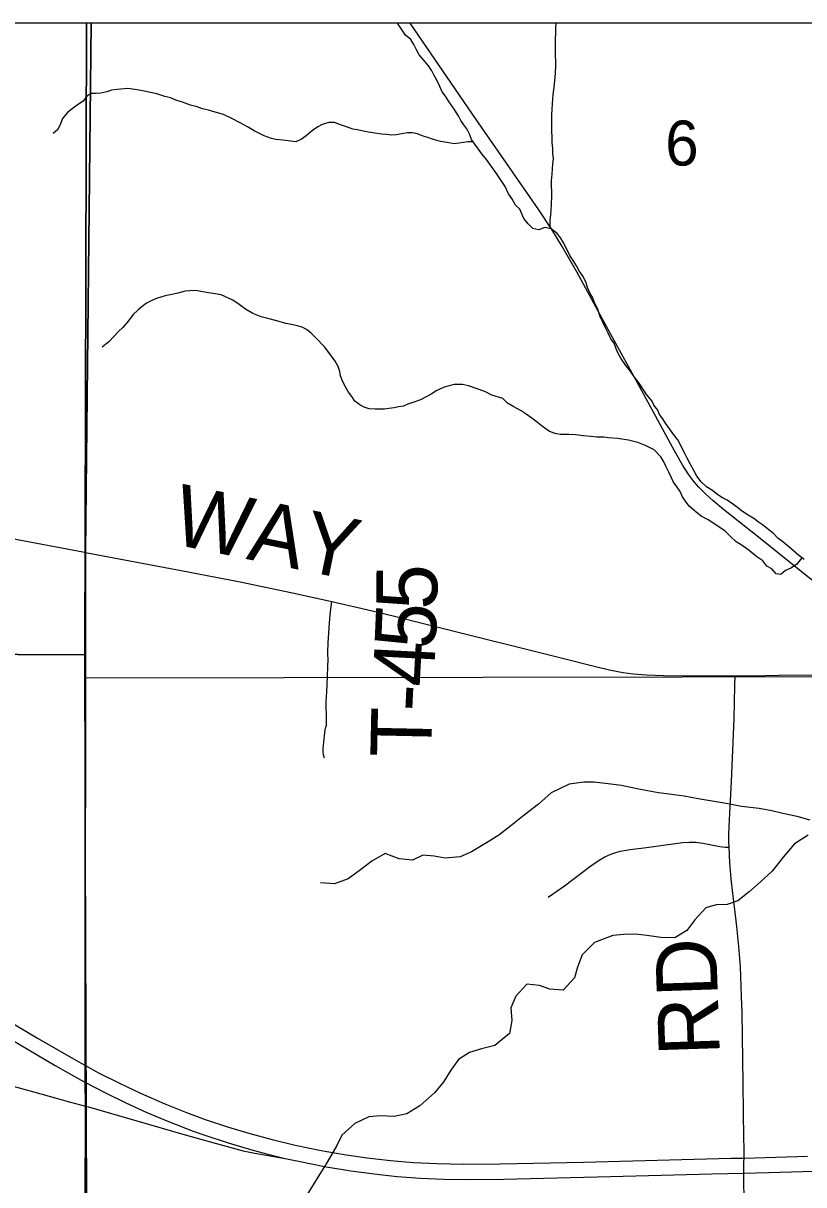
# Model space of a CAD drawing. Extents: x 0 to 34, y 0 to 22.
# Drawn here: x 5.719 to 6.446, y 19.817 to 20.9 of the extents above; entities that cross this region are included whole.
import ezdxf

# ---------------------------------------------------------------- set-up
doc = ezdxf.new("R2010")
doc.units = 0
for name, color, linetype in [('GM_X_County_Road', 7, 'Continuous'), ('GM_X_County_Road_Text', 7, 'Continuous'), ('GM_X_Minor_River', 7, 'Continuous'), ('GM_X_Section', 7, 'Continuous'), ('GM_X_Section_Text', 7, 'Continuous'), ('GM_X_State_Route', 7, 'Continuous'), ('GM_X_Township_Road', 7, 'Continuous'), ('GM_X_Township_Road_Text', 7, 'Continuous'), ('GM_X_Unincorporated', 7, 'Continuous'), ('GM_X_US_Route', 7, 'Continuous')]:
    doc.layers.add(name, color=color, linetype=linetype)

msp = doc.modelspace()

# ---------------------------------------------------------------- linework, layer by layer
at = {"layer": 'GM_X_County_Road'}
for points in [[(5.1695, 20.4986), (5.1854, 20.4986), (5.2065, 20.4983), (5.2294, 20.4982), (5.2496, 20.4977), (5.2723, 20.4972), (5.283, 20.4965), (5.2939, 20.4954), (5.3034, 20.4942), (5.3248, 20.4906), (5.3554, 20.485), (5.5022, 20.458), (5.5359, 20.4518), (5.6032, 20.4392), (5.6277, 20.4348), (5.7314, 20.4153), (5.7741, 20.4072), (5.7768, 20.4067)], [(5.7768, 20.4067), (5.8658, 20.3898), (5.9207, 20.3791), (5.9694, 20.369), (6.0063, 20.3609)], [(6.0063, 20.3609), (6.0331, 20.3547), (6.0633, 20.3474), (6.0904, 20.3407), (6.1327, 20.3302), (6.19, 20.3159), (6.2235, 20.3073), (6.2443, 20.3021), (6.253, 20.2999), (6.261, 20.298), (6.2661, 20.297), (6.2777, 20.2947), (6.287, 20.2935), (6.2995, 20.2924), (6.3151, 20.2918), (6.3493, 20.2915), (6.3791, 20.2915), (6.382, 20.2915)], [(6.382, 20.2915), (6.3969, 20.2916), (6.4231, 20.2921), (6.4788, 20.2924), (6.5063, 20.2926)]]:
    msp.add_lwpolyline(points, dxfattribs=at)
at = {"layer": 'GM_X_Minor_River'}
for points in [[(6.1626, 20.7551), (6.1591, 20.7608), (6.1548, 20.7664), (6.1502, 20.7728), (6.1459, 20.7781), (6.1428, 20.7826), (6.1394, 20.7871), (6.1363, 20.7916), (6.1347, 20.7958), (6.1319, 20.8015), (6.1292, 20.8052), (6.1265, 20.8094), (6.1242, 20.8135), (6.1195, 20.8207), (6.1153, 20.8271), (6.1122, 20.832), (6.1091, 20.8361), (6.1067, 20.841), (6.104, 20.847), (6.1016, 20.8512), (6.0993, 20.8557), (6.0962, 20.8602), (6.0916, 20.8659), (6.0877, 20.8704), (6.085, 20.8753), (6.0826, 20.8802), (6.0799, 20.8847), (6.0749, 20.8888), (6.0679, 20.899), (6.0673, 20.9)], [(6.2097, 20.7084), (6.2095, 20.7163), (6.2102, 20.7216), (6.2105, 20.7254), (6.2108, 20.7315), (6.2111, 20.7383), (6.2109, 20.7531), (6.2116, 20.7592), (6.2119, 20.7642), (6.2122, 20.7687), (6.2126, 20.7737), (6.2121, 20.7782), (6.2121, 20.7831), (6.2116, 20.7888), (6.2115, 20.7945), (6.2111, 20.7991), (6.211, 20.8029), (6.2113, 20.8101), (6.2113, 20.815), (6.2116, 20.8196), (6.2122, 20.8295), (6.2125, 20.8333), (6.2132, 20.8405), (6.2139, 20.8462), (6.2146, 20.8535), (6.2149, 20.8607), (6.2147, 20.8736), (6.2146, 20.8793), (6.2145, 20.885), (6.2148, 20.8907), (6.2148, 20.8956), (6.2153, 20.9)], [(6.1379, 20.7893), (6.1329, 20.7893), (6.1249, 20.7881), (6.1203, 20.7876), (6.1135, 20.7887), (6.1074, 20.7897), (6.1009, 20.7915), (6.0955, 20.7934), (6.0913, 20.7948), (6.086, 20.7967), (6.0814, 20.7977), (6.0768, 20.7977), (6.0662, 20.796), (6.062, 20.7956), (6.0571, 20.7963), (6.0525, 20.7966), (6.0483, 20.7973), (6.0422, 20.798), (6.0369, 20.799), (6.03, 20.8005), (6.0258, 20.8012), (6.0197, 20.8034), (6.0144, 20.8052), (6.0086, 20.8074), (6.0033, 20.8073), (5.9973, 20.8057), (5.9931, 20.8034), (5.9882, 20.7999), (5.9822, 20.7949), (5.978, 20.7918), (5.9727, 20.7894), (5.9606, 20.7908), (5.9541, 20.7915), (5.9499, 20.7926), (5.943, 20.7951), (5.9338, 20.7996), (5.9277, 20.8033), (5.9208, 20.807), (5.9131, 20.8111), (5.9051, 20.8148), (5.8975, 20.8169), (5.8914, 20.8188), (5.8856, 20.8202), (5.8807, 20.822), (5.8746, 20.8235), (5.8669, 20.8264), (5.8608, 20.8282), (5.8562, 20.8304), (5.8505, 20.8315), (5.8432, 20.8341), (5.8329, 20.8362), (5.8249, 20.838), (5.8162, 20.839), (5.8063, 20.8381), (5.801, 20.8377), (5.7964, 20.8361), (5.7911, 20.8349), (5.7866, 20.8344), (5.782, 20.8344), (5.7778, 20.832), (5.7745, 20.8274), (5.7703, 20.8244), (5.7654, 20.8212), (5.7602, 20.817), (5.7553, 20.8112), (5.7531, 20.8051), (5.7505, 20.8005), (5.7464, 20.7971)], [(6.4464, 20.4), (6.4414, 20.4037), (6.4337, 20.4104), (6.4264, 20.4164), (6.4218, 20.4198), (6.4179, 20.4239), (6.4118, 20.4288), (6.4075, 20.4325), (6.4037, 20.4347), (6.3995, 20.4381), (6.3941, 20.4414), (6.388, 20.4455), (6.3841, 20.4485), (6.3784, 20.4526), (6.3745, 20.4552), (6.3703, 20.4575), (6.3657, 20.4604), (6.3607, 20.4642), (6.3553, 20.4679), (6.3503, 20.4724), (6.3461, 20.4776), (6.3434, 20.4829), (6.3399, 20.4893), (6.3371, 20.4946), (6.3348, 20.4995), (6.3285, 20.5116), (6.3239, 20.5176), (6.3212, 20.5214), (6.3169, 20.527), (6.3146, 20.5312), (6.3115, 20.5353), (6.3099, 20.5391), (6.3061, 20.544), (6.3045, 20.5477), (6.2998, 20.5534), (6.296, 20.559), (6.2925, 20.5643), (6.2882, 20.5699), (6.284, 20.576), (6.2801, 20.5808), (6.2754, 20.5876), (6.2731, 20.5921), (6.2711, 20.5963), (6.2692, 20.6016), (6.2661, 20.6057), (6.2637, 20.611), (6.261, 20.6159), (6.259, 20.6208), (6.2559, 20.6272), (6.2539, 20.6333), (6.2508, 20.6393), (6.2492, 20.6439), (6.2469, 20.648), (6.2445, 20.6537), (6.243, 20.6578), (6.2402, 20.6639), (6.2367, 20.6691), (6.234, 20.6737), (6.2309, 20.6789), (6.2278, 20.6835), (6.2262, 20.6876), (6.2216, 20.6959), (6.2196, 20.6997), (6.2161, 20.7038), (6.2104, 20.7083), (6.2046, 20.7094), (6.199, 20.7074), (6.1936, 20.7085), (6.189, 20.7129), (6.1851, 20.7178), (6.1812, 20.7265), (6.1774, 20.7303), (6.1739, 20.7367), (6.1708, 20.7408), (6.1676, 20.7476), (6.1653, 20.7514), (6.1626, 20.7551)], [(5.8913, 20.6486), (5.884, 20.65), (5.8795, 20.6507), (5.8738, 20.6506), (5.8696, 20.6502), (5.8628, 20.6482), (5.8586, 20.6474), (5.851, 20.6458), (5.8438, 20.6438), (5.8396, 20.6422), (5.8336, 20.6391), (5.8294, 20.636), (5.8253, 20.6325), (5.8212, 20.6283), (5.8167, 20.6225), (5.8114, 20.6164), (5.8073, 20.6125), (5.8032, 20.6079), (5.7983, 20.6029), (5.7923, 20.5979)], [(6.444, 20.4017), (6.4392, 20.3953), (6.4339, 20.3918), (6.429, 20.3899), (6.4245, 20.386), (6.4203, 20.3867), (6.416, 20.3912), (6.4115, 20.3938), (6.4076, 20.3987), (6.4022, 20.4024), (6.3949, 20.4084), (6.3876, 20.4136), (6.383, 20.4166), (6.3776, 20.4215), (6.3726, 20.4263), (6.3669, 20.4304), (6.3569, 20.4371), (6.3504, 20.4405), (6.3454, 20.4446), (6.3392, 20.4498), (6.3357, 20.4543), (6.333, 20.4585), (6.3307, 20.4634), (6.328, 20.4675), (6.3245, 20.472), (6.3225, 20.4762), (6.3202, 20.4815), (6.3174, 20.4871), (6.3151, 20.4917), (6.3128, 20.4958), (6.3066, 20.5022), (6.2989, 20.5059), (6.2913, 20.5092), (6.2825, 20.5114), (6.2722, 20.5127), (6.2639, 20.5134), (6.2597, 20.5141), (6.2532, 20.514), (6.2479, 20.5147), (6.2406, 20.5154), (6.2334, 20.5164), (6.2269, 20.5167), (6.2193, 20.5166), (6.2151, 20.5173), (6.209, 20.5195), (6.2025, 20.524), (6.1979, 20.5277), (6.1925, 20.5318), (6.1871, 20.5355), (6.1825, 20.5385), (6.1756, 20.5422), (6.1699, 20.5459), (6.1656, 20.5501), (6.1553, 20.5533), (6.1488, 20.5567), (6.1335, 20.5618), (6.1278, 20.5632), (6.1202, 20.5631), (6.1107, 20.5607), (6.1035, 20.5572), (6.0994, 20.5545), (6.0888, 20.549), (6.0816, 20.5463), (6.0771, 20.5447), (6.0729, 20.5431), (6.0684, 20.5423), (6.0642, 20.5415), (6.0593, 20.5407), (6.0551, 20.5402), (6.0467, 20.5401), (6.041, 20.5404), (6.0364, 20.5419), (6.0322, 20.5441), (6.0276, 20.5475), (6.0249, 20.552), (6.0218, 20.5561), (6.0179, 20.5625), (6.0159, 20.5671), (6.0144, 20.5712), (6.0136, 20.5754), (6.012, 20.5799), (6.0092, 20.5848), (6.0058, 20.5897), (5.9996, 20.598), (5.9911, 20.607), (5.9868, 20.6111), (5.9826, 20.6145), (5.9784, 20.6167), (5.9738, 20.6178), (5.9685, 20.6192), (5.9632, 20.6199), (5.9548, 20.6225), (5.9464, 20.6246), (5.9403, 20.6264), (5.9326, 20.6294), (5.9257, 20.6335), (5.9199, 20.6376), (5.9138, 20.6417), (5.9031, 20.6468), (5.8955, 20.6479), (5.8913, 20.6486)], [(6.4517, 20.1571), (6.4396, 20.1605), (6.4263, 20.1634), (6.416, 20.1656), (6.4043, 20.1678), (6.388, 20.1699), (6.3736, 20.1725), (6.3569, 20.1754), (6.3474, 20.1768), (6.3345, 20.1794), (6.3205, 20.1812), (6.3106, 20.1826), (6.3004, 20.1844), (6.289, 20.1866), (6.2761, 20.1892), (6.2636, 20.191), (6.2507, 20.1924), (6.2409, 20.1923), (6.2273, 20.1907), (6.2106, 20.1826), (6.1986, 20.1719), (6.1854, 20.1616), (6.173, 20.1516), (6.1617, 20.1432), (6.1519, 20.1367), (6.1364, 20.1275), (6.1258, 20.1228), (6.1118, 20.1216), (6.1016, 20.1234), (6.091, 20.1245), (6.0812, 20.1198), (6.069, 20.1209), (6.0558, 20.1261), (6.0433, 20.1188), (6.0328, 20.1107), (6.0215, 20.1023), (6.0086, 20.0977), (5.9957, 20.0987)], [(6.4499, 20.1431), (6.4371, 20.135), (6.4266, 20.1224), (6.4164, 20.1095), (6.4055, 20.0995), (6.395, 20.0903), (6.3844, 20.0819), (6.3746, 20.0784), (6.3644, 20.078), (6.3545, 20.0753), (6.3444, 20.0642), (6.3369, 20.0543), (6.3256, 20.0474), (6.3127, 20.0476), (6.2998, 20.0494), (6.2892, 20.0509), (6.2782, 20.0504), (6.268, 20.0496), (6.251, 20.043), (6.2393, 20.0315), (6.2352, 20.0201), (6.2323, 20.0099), (6.2218, 19.9984), (6.2093, 19.9994), (6.1998, 20.0028), (6.188, 20.0042), (6.1775, 19.9931), (6.173, 19.9821), (6.1739, 19.9704), (6.1717, 19.9582), (6.1581, 19.9471), (6.1456, 19.944), (6.1343, 19.9405), (6.1241, 19.934), (6.117, 19.924), (6.1106, 19.9134), (6.102, 19.9031), (6.0881, 19.8908), (6.076, 19.8832), (6.0643, 19.8808), (6.0514, 19.8814), (6.0408, 19.8806), (6.0276, 19.8744), (6.0155, 19.8634), (6.0107, 19.8538), (6.0017, 19.8382), (5.9923, 19.8226), (5.9833, 19.8081)]]:
    msp.add_lwpolyline(points, dxfattribs=at)
at = {"layer": 'GM_X_Section'}
for points in [[(5.415, 19.3104), (5.7798, 19.3134), (5.776, 20.2897), (5.7762, 20.3113), (4.7808, 20.316), (4.783, 19.4891), (5.415, 19.4891)], [(5.776, 20.2897), (6.8888, 20.2917), (6.9057, 19.2783), (5.7801, 19.2683), (5.7798, 19.3134)]]:
    msp.add_lwpolyline(points, close=True, dxfattribs=at)
at = {"layer": 'GM_X_State_Route'}
msp.add_lwpolyline([(6.5254, 20.323), (6.5192, 20.3284), (6.4877, 20.3537), (6.4512, 20.3827), (6.4052, 20.4197), (6.3711, 20.4466), (6.3615, 20.4546), (6.3546, 20.4609), (6.348, 20.4676), (6.3439, 20.4723), (6.3383, 20.4799), (6.3332, 20.4878), (6.3254, 20.5013), (6.2927, 20.5613), (6.2659, 20.6104), (6.2347, 20.6677), (6.2208, 20.6919), (6.2111, 20.7078), (6.1991, 20.7259), (6.169, 20.7694), (6.1406, 20.8102), (6.1056, 20.8615), (6.0793, 20.9)], dxfattribs=at)
at = {"layer": 'GM_X_Township_Road'}
for points in [[(5.7764, 19.7938), (5.7766, 19.8909), (5.7765, 19.9131), (5.7764, 19.9288), (5.7766, 20.4072), (5.7818, 20.9), (2.1, 20.9)], [(8.9, 20.9), (5.7818, 20.9), (5.7766, 20.4072), (5.7764, 19.9288), (5.7765, 19.9131), (5.7766, 19.8909), (5.7764, 19.7938)], [(5.9992, 20.2149), (5.9985, 20.2178), (5.9981, 20.2209), (5.9981, 20.2239), (5.9986, 20.23), (5.999, 20.2328), (5.9993, 20.2359), (5.9997, 20.2386), (6, 20.2413), (6.0005, 20.2438), (6.0012, 20.2456), (6.0013, 20.2483), (6.0012, 20.2543), (6.001, 20.2635), (6.001, 20.2666), (6.0012, 20.2728), (6.0015, 20.2759), (6.002, 20.2911), (6.0025, 20.3004), (6.0029, 20.3068), (6.0027, 20.3081), (6.0025, 20.3104), (6.0025, 20.3133), (6.0026, 20.3163), (6.0028, 20.3194), (6.0029, 20.3224), (6.0034, 20.3317), (6.0041, 20.341), (6.0049, 20.3517), (6.0056, 20.3563), (6.0063, 20.3609)], [(6.3763, 20.132), (6.3762, 20.1365), (6.3762, 20.1438), (6.3764, 20.1512), (6.3771, 20.1637), (6.3785, 20.1931), (6.3809, 20.2514), (6.3818, 20.2827), (6.382, 20.2915)], [(6.2076, 20.0853), (6.2228, 20.0959), (6.2474, 20.1146), (6.2551, 20.1198), (6.2604, 20.1229), (6.266, 20.1254), (6.269, 20.1264), (6.2749, 20.128), (6.2841, 20.1296), (6.2994, 20.1316), (6.3238, 20.135), (6.333, 20.1362), (6.3391, 20.1365), (6.3453, 20.1364), (6.3518, 20.1356), (6.3584, 20.1344), (6.3678, 20.1325), (6.3726, 20.1319), (6.3763, 20.132)], [(6.3901, 19.828), (6.3901, 19.8379), (6.3902, 19.8418), (6.3904, 19.85), (6.3901, 19.8617), (6.3898, 19.8842), (6.3894, 19.9122), (6.3884, 19.9773), (6.388, 19.9928), (6.3868, 20.0207), (6.3855, 20.0393), (6.3836, 20.0578), (6.3813, 20.0762), (6.3798, 20.0886), (6.3782, 20.1023), (6.3771, 20.1172), (6.3763, 20.132)], [(6.3904, 19.8009), (6.3904, 19.8037), (6.3901, 19.8212), (6.3901, 19.828)]]:
    msp.add_lwpolyline(points, dxfattribs=at)
at = {"layer": 'GM_X_Unincorporated'}
for points in [[(5.7777, 20.9), (4.7739, 20.9), (4.7808, 20.316), (5.7762, 20.3113)], [(6.889, 20.9), (5.7777, 20.9), (5.7762, 20.3113), (5.776, 20.2897), (6.8888, 20.2917)]]:
    msp.add_lwpolyline(points, close=True, dxfattribs=at)
at = {"layer": 'GM_X_US_Route'}
for points in [[(5.1444, 20.2539), (5.1454, 20.2536), (5.1495, 20.2523), (5.1602, 20.2489), (5.172, 20.245), (5.1927, 20.2383), (5.2162, 20.23), (5.2365, 20.2222), (5.2565, 20.2137), (5.2763, 20.2047), (5.2959, 20.1951), (5.3151, 20.1849), (5.3395, 20.1712), (5.4224, 20.1222), (5.4704, 20.0934), (5.636, 19.9949), (5.6893, 19.963), (5.7483, 19.9284), (5.7726, 19.9147), (5.7767, 19.9125)], [(5.6521, 20.0015), (5.7321, 19.9538), (5.7697, 19.9321), (5.7766, 19.9283)], [(5.7766, 19.9283), (5.7888, 19.9216), (5.8082, 19.9117), (5.8278, 19.9024), (5.8506, 19.8925), (5.8708, 19.8844), (5.8883, 19.878), (5.9089, 19.8711), (5.9297, 19.8649), (5.9507, 19.8592), (5.9719, 19.8542), (5.9962, 19.8492), (6.0176, 19.8453), (6.0391, 19.8422), (6.0607, 19.8397), (6.0824, 19.8379), (6.1041, 19.8369), (6.129, 19.8364), (6.1631, 19.8365), (6.2407, 19.8382), (6.3783, 19.8419), (6.3902, 19.8418), (6.4492, 19.8438)], [(5.7094, 19.9091), (5.7352, 19.9018), (5.7627, 19.8942), (5.7768, 19.8904)], [(5.7767, 19.9125), (5.7946, 19.9031), (5.8141, 19.8935), (5.8338, 19.8845), (5.8539, 19.8761), (5.877, 19.8672), (5.887, 19.8636), (5.9097, 19.8562), (5.9326, 19.8494), (5.9467, 19.8456), (5.9627, 19.8417)], [(5.7768, 19.8904), (5.7794, 19.8897), (5.8696, 19.8637), (5.8975, 19.8558), (5.9236, 19.8487), (5.9343, 19.8465), (5.9627, 19.8417)], [(6.3901, 19.828), (6.413, 19.8287), (6.4874, 19.8307), (6.5375, 19.8321), (6.5944, 19.8337), (6.6691, 19.8354), (6.686, 19.8357), (6.7389, 19.8369), (6.804, 19.8387), (6.8824, 19.8407), (6.9312, 19.8415), (6.9934, 19.843), (7.1268, 19.8461), (7.1827, 19.8473), (7.3503, 19.8511), (7.4496, 19.8538), (7.5557, 19.857), (7.58, 19.8576), (7.6132, 19.8587), (7.6697, 19.86), (7.7229, 19.8613), (7.7733, 19.8625)], [(5.9627, 19.8417), (5.9751, 19.8391), (5.9994, 19.8343), (6.0239, 19.8302), (6.0455, 19.8272), (6.0671, 19.825), (6.0888, 19.8234), (6.1105, 19.8225), (6.1354, 19.8221), (6.1664, 19.8225), (6.2659, 19.8249), (6.3601, 19.8274), (6.3901, 19.828)]]:
    msp.add_lwpolyline(points, dxfattribs=at)

# ---------------------------------------------------------------- texts
at = {"layer": 'GM_X_County_Road_Text'}
msp.add_text('WAY', height=0.05682, rotation=348.4657, dxfattribs=at).set_placement((5.8554, 20.415))
at = {"layer": 'GM_X_Section_Text'}
msp.add_text('6', height=0.0419, rotation=0, dxfattribs=at).set_placement((6.3168, 20.7673))
at = {"layer": 'GM_X_Township_Road_Text'}
for s, height, rotation, p in [('5', 0.0568, 89.3392, (6.1042, 20.3531)), ('5', 0.0568, 87.5373, (6.1026, 20.3161)), ('4', 0.0568, 87.0193, (6.1008, 20.2806)), ('-', 0.0568, 87.1848, (6.0997, 20.2574)), ('T', 0.0568, 88.7871, (6.0988, 20.2153)), ('RD', 0.05682, 91.9234, (6.3677, 19.9383))]:
    msp.add_text(s, height=height, rotation=rotation, dxfattribs=at).set_placement(p)

doc.saveas('drawing.dxf')
